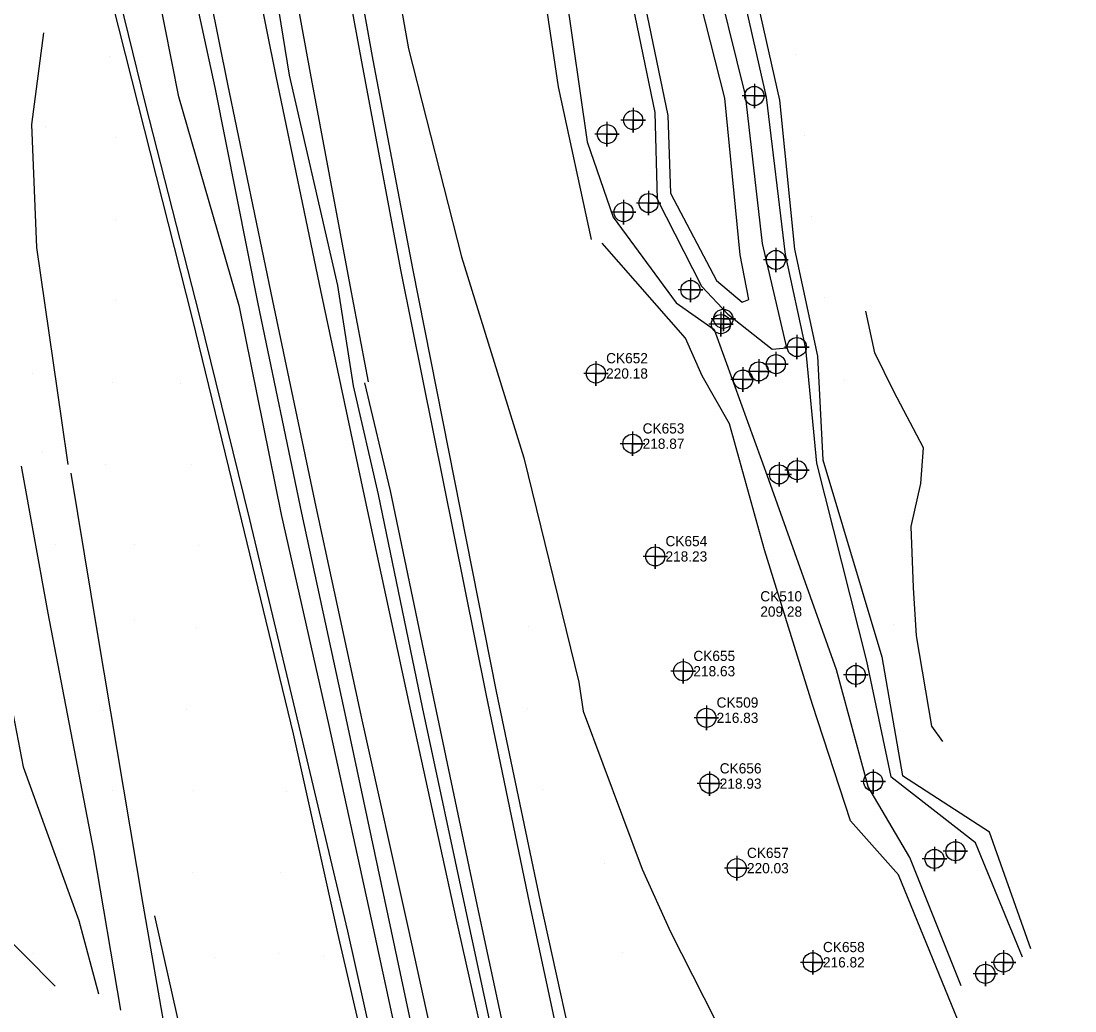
# Model space of a CAD drawing. Extents: x 1941547 to 1942851, y 663002 to 668358.
# Drawn here: x 1941984 to 1942242, y 666212 to 666454.4 of the extents above; entities that cross this region are included whole.
import ezdxf

# ---------------------------------------------------------------- set-up
doc = ezdxf.new("R2010")
doc.units = 0
for name, color, linetype in [('CTL GPS Vertical Cogo Elevation', 7, 'Continuous'), ('CTL NGS Vertical CELL', 7, 'Continuous'), ('Exist DTM Breakline Underwater', 7, 'Continuous'), ('Exist DTM Drainline Cogo Elevation', 7, 'Continuous'), ('Exist DTM Regular Point Underwater CELL', 7, 'Continuous'), ('Exist Property Iron Pin Cogo Number', 7, 'Continuous'), ('Exist Roads EOP Cogo Point CELL', 7, 'Continuous'), ('Exist Roads EOT', 7, 'Continuous'), ('Exist Utilities Telephone UG Cable SUE LOS C Cogo Elevation', 7, 'Continuous'), ('Exist Utilities Telephone UG FO SUE LOS C Cogo Elevation', 7, 'Continuous'), ('PH Exist DTM Breakline', 7, 'Continuous'), ('PH Exist DTM Point', 7, 'Continuous')]:
    doc.layers.add(name, color=color, linetype=linetype)

msp = doc.modelspace()

# ---------------------------------------------------------------- linework, layer by layer
at = {"layer": 'CTL NGS Vertical CELL'}
for points in [[(1942135.5, 665887.91), (1942127.19, 665926.67), (1942116.47, 665977.64), (1942106.06, 666031.75), (1942095.67, 666078.28), (1942084.99, 666129.32), (1942073.59, 666178.98), (1942061.57, 666231.07), (1942050.7, 666279.83), (1942038.07, 666332.06), (1942025.94, 666381.57), (1942012.73, 666433.79), (1941999.93, 666484.44)], [(1942137.2, 665888.17), (1942129.75, 665927.19), (1942119.82, 665978.57), (1942108.24, 666032.34), (1942098.02, 666079.16), (1942087.31, 666129.73), (1942075.59, 666179.6), (1942064.03, 666231.55), (1942052.46, 666280.06), (1942040, 666332.34), (1942027.67, 666382.39), (1942014.48, 666434.14), (1942001.98, 666485.22)]]:
    msp.add_lwpolyline(points, dxfattribs=at)
at = {"layer": 'Exist DTM Breakline Underwater'}
for points in [[(1942091.77, 666678.75), (1942095.7, 666642.98), (1942101.32, 666613.67), (1942106.49, 666587.88), (1942111.26, 666546.73), (1942115.87, 666520.01), (1942119.06, 666486.92), (1942117.3, 666461.85), (1942122.58, 666424.87), (1942128.94, 666406.45), (1942144.41, 666385.42), (1942153.71, 666378.9), (1942158.38, 666365.82), (1942167, 666342.2), (1942183.54, 666295.61), (1942191.33, 666267.04)], [(1942132.79, 666462.93), (1942139.14, 666432.09), (1942139.71, 666410.82), (1942150.61, 666389.55), (1942156.99, 666382.62), (1942167.87, 666374.06), (1942171.46, 666374.45), (1942165.54, 666400), (1942161.38, 666436.33), (1942152.92, 666470.32), (1942144.22, 666513.65), (1942142.34, 666548.69)], [(1942144.62, 666548.74), (1942148.17, 666515.06), (1942159.19, 666467.53), (1942166.42, 666435.81), (1942171.04, 666397.24), (1942176, 666374.23), (1942178.76, 666346.16), (1942190.96, 666297.66), (1942196.91, 666269.32)], [(1942229.17, 666225.2), (1942217.66, 666253.19), (1942196.91, 666269.32)], [(1942214.17, 666218.12), (1942201.55, 666249.54), (1942191.33, 666267.04)]]:
    msp.add_lwpolyline(points, dxfattribs=at)
at = {"layer": 'Exist DTM Drainline Cogo Elevation'}
for points in [[(1942124.73, 666371.13), (1942124.73, 666365.13), (1942124.73, 666368.13), (1942127.73, 666368.13), (1942121.73, 666368.13)], [(1942124.73, 666371.13), (1942124.73, 666365.13), (1942124.73, 666368.13), (1942127.73, 666368.13), (1942121.73, 666368.13)], [(1942133.67, 666353.93), (1942133.67, 666347.93), (1942133.67, 666350.93), (1942136.67, 666350.93), (1942130.67, 666350.93)], [(1942133.67, 666353.93), (1942133.67, 666347.93), (1942133.67, 666350.93), (1942136.67, 666350.93), (1942130.67, 666350.93)], [(1942139.26, 666326.32), (1942139.26, 666320.32), (1942139.26, 666323.32), (1942142.26, 666323.32), (1942136.26, 666323.32)], [(1942139.26, 666326.32), (1942139.26, 666320.32), (1942139.26, 666323.32), (1942142.26, 666323.32), (1942136.26, 666323.32)], [(1942146.09, 666298.21), (1942146.09, 666292.21), (1942146.09, 666295.21), (1942149.09, 666295.21), (1942143.09, 666295.21)], [(1942146.09, 666298.21), (1942146.09, 666292.21), (1942146.09, 666295.21), (1942149.09, 666295.21), (1942143.09, 666295.21)], [(1942151.77, 666286.79), (1942151.77, 666280.79), (1942151.77, 666283.79), (1942154.77, 666283.79), (1942148.77, 666283.79)], [(1942152.54, 666270.67), (1942152.54, 666264.67), (1942152.54, 666267.67), (1942155.54, 666267.67), (1942149.54, 666267.67)], [(1942152.54, 666270.67), (1942152.54, 666264.67), (1942152.54, 666267.67), (1942155.54, 666267.67), (1942149.54, 666267.67)], [(1942159.21, 666249.97), (1942159.21, 666243.97), (1942159.21, 666246.97), (1942162.21, 666246.97), (1942156.21, 666246.97)], [(1942159.21, 666249.97), (1942159.21, 666243.97), (1942159.21, 666246.97), (1942162.21, 666246.97), (1942156.21, 666246.97)], [(1942177.81, 666226.9), (1942177.81, 666220.9), (1942177.81, 666223.9), (1942180.81, 666223.9), (1942174.81, 666223.9)], [(1942177.81, 666226.9), (1942177.81, 666220.9), (1942177.81, 666223.9), (1942180.81, 666223.9), (1942174.81, 666223.9)]]:
    msp.add_lwpolyline(points, dxfattribs=at)
for centre in [(1942124.73, 666368.13), (1942124.73, 666368.13), (1942133.67, 666350.93), (1942133.67, 666350.93), (1942139.26, 666323.32), (1942139.26, 666323.32), (1942146.09, 666295.21), (1942146.09, 666295.21), (1942151.77, 666283.79), (1942152.54, 666267.67), (1942152.54, 666267.67), (1942159.21, 666246.97), (1942159.21, 666246.97), (1942177.81, 666223.9), (1942177.81, 666223.9)]:
    msp.add_circle(centre, 2.34, dxfattribs=at)
at = {"layer": 'Exist DTM Regular Point Underwater CELL'}
for points in [[(1942163.51, 666439.1), (1942163.51, 666433.1), (1942163.51, 666436.1), (1942166.51, 666436.1), (1942160.51, 666436.1)], [(1942133.86, 666433.19), (1942133.86, 666427.19), (1942133.86, 666430.19), (1942136.86, 666430.19), (1942130.86, 666430.19)], [(1942127.44, 666429.74), (1942127.44, 666423.74), (1942127.44, 666426.74), (1942130.44, 666426.74), (1942124.44, 666426.74)], [(1942137.63, 666412.88), (1942137.63, 666406.88), (1942137.63, 666409.88), (1942140.63, 666409.88), (1942134.63, 666409.88)], [(1942131.5, 666410.64), (1942131.5, 666404.64), (1942131.5, 666407.64), (1942134.5, 666407.64), (1942128.5, 666407.64)], [(1942168.76, 666398.94), (1942168.76, 666392.94), (1942168.76, 666395.94), (1942171.76, 666395.94), (1942165.76, 666395.94)], [(1942147.87, 666391.59), (1942147.87, 666385.59), (1942147.87, 666388.59), (1942150.87, 666388.59), (1942144.87, 666388.59)], [(1942155.92, 666384.51), (1942155.92, 666378.51), (1942155.92, 666381.51), (1942158.92, 666381.51), (1942152.92, 666381.51)], [(1942155.33, 666383.22), (1942155.33, 666377.22), (1942155.33, 666380.22), (1942158.33, 666380.22), (1942152.33, 666380.22)], [(1942173.92, 666377.61), (1942173.92, 666371.61), (1942173.92, 666374.61), (1942176.92, 666374.61), (1942170.92, 666374.61)], [(1942168.8, 666373.41), (1942168.8, 666367.41), (1942168.8, 666370.41), (1942171.8, 666370.41), (1942165.8, 666370.41)], [(1942164.63, 666371.64), (1942164.63, 666365.64), (1942164.63, 666368.64), (1942167.63, 666368.64), (1942161.63, 666368.64)], [(1942160.73, 666369.64), (1942160.73, 666363.64), (1942160.73, 666366.64), (1942163.73, 666366.64), (1942157.73, 666366.64)], [(1942173.97, 666347.46), (1942173.97, 666341.46), (1942173.97, 666344.46), (1942176.97, 666344.46), (1942170.97, 666344.46)], [(1942169.57, 666346.42), (1942169.57, 666340.42), (1942169.57, 666343.42), (1942172.57, 666343.42), (1942166.57, 666343.42)], [(1942188.34, 666297.29), (1942188.34, 666291.29), (1942188.34, 666294.29), (1942191.34, 666294.29), (1942185.34, 666294.29)], [(1942192.6, 666271.17), (1942192.6, 666265.17), (1942192.6, 666268.17), (1942195.6, 666268.17), (1942189.6, 666268.17)], [(1942207.61, 666252.23), (1942207.61, 666246.23), (1942207.61, 666249.23), (1942210.61, 666249.23), (1942204.61, 666249.23)], [(1942212.73, 666254.11), (1942212.73, 666248.11), (1942212.73, 666251.11), (1942215.73, 666251.11), (1942209.73, 666251.11)], [(1942224.51, 666226.87), (1942224.51, 666220.87), (1942224.51, 666223.87), (1942227.51, 666223.87), (1942221.51, 666223.87)], [(1942220.06, 666224.09), (1942220.06, 666218.09), (1942220.06, 666221.09), (1942223.06, 666221.09), (1942217.06, 666221.09)]]:
    msp.add_lwpolyline(points, dxfattribs=at)
for centre in [(1942163.51, 666436.1), (1942133.86, 666430.19), (1942127.44, 666426.74), (1942137.63, 666409.88), (1942131.5, 666407.64), (1942168.76, 666395.94), (1942147.87, 666388.59), (1942155.92, 666381.51), (1942155.33, 666380.22), (1942173.92, 666374.61), (1942164.63, 666368.64), (1942168.8, 666370.41), (1942160.73, 666366.64), (1942169.57, 666343.42), (1942173.97, 666344.46), (1942188.34, 666294.29), (1942192.6, 666268.17), (1942212.73, 666251.11), (1942207.61, 666249.23), (1942224.51, 666223.87), (1942220.06, 666221.09)]:
    msp.add_circle(centre, 2.34, dxfattribs=at)
at = {"layer": 'Exist Property Iron Pin Cogo Number'}
msp.add_lwpolyline([(1942228.27, 665631.91), (1942215.35, 665690.54), (1942203.38, 665744.37), (1942193.36, 665791.05), (1942181.96, 665842.56), (1942170.96, 665893.33), (1942160.58, 665938.17), (1942155.29, 665961.96), (1942149.62, 665986.57), (1942137.61, 666038.72), (1942126.12, 666087.51), (1942115.02, 666136.31), (1942103.6, 666187.08), (1942093.09, 666235.61), (1942082.3, 666286.44), (1942071.51, 666338.53), (1942065.4, 666365.11), (1942061.56, 666389.7), (1942049.68, 666441.21), (1942041.5, 666492.09), (1942031.83, 666544.21), (1942023.2, 666595.06), (1942013.62, 666656.61), (1942008.43, 666689.96)], dxfattribs=at)
at = {"layer": 'Exist Roads EOT'}
for points in [[(1942239.89, 665634.47), (1942227.05, 665692.43), (1942215.28, 665746.03), (1942204.9, 665793.1), (1942193.81, 665844.48), (1942182.41, 665896.46), (1942173.11, 665940.53), (1942162.51, 665989.38), (1942151.29, 666040.92), (1942140.43, 666090.67), (1942129.8, 666139.39), (1942119.07, 666189.07), (1942108.58, 666238.14), (1942097.82, 666289.68), (1942077.07, 666393.11), (1942067.43, 666444.43), (1942058.06, 666495.58), (1942049.26, 666547.02), (1942041.05, 666598.14), (1942031.78, 666658.51), (1942026.7, 666693.35)], [(1942216.33, 665631.64), (1942203.63, 665688.68), (1942191.56, 665741.16), (1942181.15, 665788.55), (1942170.15, 665839.04), (1942158.52, 665891.09), (1942148.46, 665935.11), (1942136.79, 665984.14), (1942124.38, 666035.44), (1942112.67, 666084.11), (1942101.18, 666132.69), (1942089.27, 666184.63), (1942078.82, 666232.22), (1942067.51, 666283.26), (1942056.28, 666335.48), (1942045.64, 666385.95), (1942034.6, 666439.01), (1942024.01, 666491.71), (1942014.76, 666541.49), (1942006.11, 666591.53), (1942001.31, 666620.24), (1941993.82, 666637.67), (1941979.79, 666649.91), (1941961.73, 666657.29)], [(1942154.73, 665961.88), (1942148.9, 665986.47), (1942136.37, 666038.07), (1942124.51, 666087.33), (1942112.95, 666135.81), (1942101.29, 666186.74), (1942090.44, 666235.06), (1942079.42, 666285.53), (1942068.09, 666338.16), (1942062.34, 666365.05), (1942057.42, 666388.45), (1942046.52, 666440.57), (1942036.47, 666490.47), (1942026.54, 666543.55), (1942017.93, 666593.73), (1942007.82, 666655.78)], [(1942069.09, 666366.11), (1942064.53, 666389.77), (1942054.87, 666441.71), (1942045.44, 666493.08), (1942037.04, 666544.89), (1942028.85, 666595.58), (1942019.74, 666656.24)], [(1942155.67, 665962.14), (1942150.22, 665986.74), (1942138.88, 666038.57), (1942127.93, 666087.9), (1942117.32, 666136.64), (1942106.41, 666187.82), (1942095.96, 666236.54), (1942085.34, 666286.97), (1942074.48, 666339.36), (1942068.19, 666365.82)]]:
    msp.add_lwpolyline(points, dxfattribs=at)
at = {"layer": 'Exist Utilities Telephone UG Cable SUE LOS C Cogo Elevation'}
for points in [[(1942241.99, 665634.93), (1942229.18, 665693.32), (1942218.46, 665746.7), (1942209.27, 665793.91), (1942197.95, 665845.25), (1942186.36, 665897.34), (1942176.03, 665941.11), (1942165.47, 665989.95), (1942154.18, 666041.36), (1942143.37, 666091.41), (1942132.79, 666139.63), (1942122, 666189.48), (1942111.14, 666238.84), (1942100.41, 666290.27), (1942079.89, 666393.87), (1942070.21, 666444.86), (1942060.95, 666496.14), (1942052.29, 666547.35), (1942044.06, 666598.94), (1942035.22, 666658.38), (1942029.81, 666693.65)], [(1942213.99, 665632.37), (1942202.16, 665688.24), (1942190.02, 665740.92), (1942178.65, 665787.73), (1942166.53, 665839.16), (1942154.86, 665890.17), (1942143.77, 665934.31), (1942131.73, 665982.91), (1942119.44, 666034.59), (1942108.8, 666082.94), (1942097.26, 666132.24), (1942084.85, 666183.55), (1942074.65, 666231.51), (1942063.8, 666282.56), (1942052.72, 666333.95), (1942042.01, 666385.23), (1942031.54, 666438.14), (1942020.1, 666490.97), (1942010.35, 666540.81), (1942001.86, 666591.1), (1941996.76, 666619.63), (1941991.94, 666636.36), (1941978.98, 666647.81), (1941961.64, 666654.67)]]:
    msp.add_lwpolyline(points, dxfattribs=at)
at = {"layer": 'Exist Utilities Telephone UG FO SUE LOS C Cogo Elevation'}
msp.add_line((1942025.01, 666198.49), (1942016.74, 666235.33), dxfattribs=at)
for points in [[(1942040.06, 666695.59), (1942044.64, 666660.9), (1942053.37, 666600.34), (1942061.1, 666549.68), (1942070.22, 666496.32), (1942078.82, 666447.64), (1942091.81, 666396.73), (1942107.09, 666347.46), (1942120.54, 666292.55), (1942121.58, 666285.4), (1942136.04, 666246.7), (1942142.99, 666231.38), (1942156.51, 666204.69), (1942176.98, 666157.07), (1942194.89, 666100.26)], [(1942123.62, 666400.94), (1942115.55, 666438.3), (1942109.62, 666478.35), (1942106.9, 666518.05), (1942100.95, 666558.27)], [(1942135.91, 666462.49), (1942142.36, 666431.3), (1942142.96, 666412.28), (1942154.22, 666390.92), (1942160.56, 666385.57), (1942162.15, 666386.27), (1942160.08, 666397.16), (1942156.25, 666435.58), (1942148.06, 666468.05), (1942141.36, 666512.94), (1942138.83, 666547.76)], [(1942148.29, 666548.23), (1942150.62, 666519.14), (1942162.38, 666467.44), (1942169.67, 666435.04), (1942173.32, 666398.58), (1942178.98, 666372.34), (1942180.25, 666347.02), (1942194.7, 666298.74), (1942199.77, 666269.61)], [(1942168.3, 665779.55), (1942157.65, 665834.34), (1942151.92, 665851.93), (1942141.5, 665888.6), (1942135.45, 665929.19), (1942125.9, 665980.59), (1942115.36, 666033.71), (1942104.57, 666081.51), (1942092.84, 666130.71), (1942081.31, 666181.18), (1942070.23, 666232.6), (1942059.43, 666281.93), (1942047.77, 666333.59), (1942037.49, 666384.47), (1942022.61, 666435.89), (1942012.32, 666487.89)], [(1941989.46, 666451.59), (1941986.52, 666429.11), (1941987.75, 666399.02), (1941993.91, 666356.59), (1941995.49, 666345.86)], [(1942187.02, 666258.54), (1942177.78, 666287.03), (1942165.96, 666324.97), (1942157.43, 666355.78), (1942150.74, 666367.59), (1942146.68, 666376.77), (1942126.23, 666400.06)], [(1941900.24, 666359.08), (1941938.41, 666335.83), (1941976.24, 666314.28), (1941984.52, 666271.75), (1941998.11, 666234.11), (1942002.98, 666216.21)], [(1942008.4, 666212.18), (1942001.81, 666251.18), (1941990.63, 666309.45), (1941984.13, 666345.39)], [(1942019.56, 666205.82), (1942013.89, 666238.19), (1942002.78, 666304.16), (1941996.3, 666343.72)], [(1941913.93, 666286.99), (1941962.33, 666248.37), (1941992.34, 666218.07)], [(1942231.16, 666227.23), (1942221.09, 666255.81), (1942199.77, 666269.61)], [(1942214.84, 666205.98), (1942198.8, 666245.36), (1942187.02, 666258.54)]]:
    msp.add_lwpolyline(points, dxfattribs=at)
at = {"layer": 'PH Exist DTM Breakline'}
msp.add_lwpolyline([(1942209.69, 666277.98), (1942206.98, 666281.73), (1942203.18, 666303.89), (1942202.44, 666315.73), (1942201.92, 666330.65), (1942204.3, 666341.15), (1942204.9, 666349.9), (1942197.69, 666363.72), (1942193.01, 666373.22), (1942190.79, 666383.37)], dxfattribs=at)
at = {"layer": 'PH Exist DTM Point'}
for p, q in [((1942005.65, 666445.85), (1942005.65, 666445.85)), ((1942173.62, 666446.38), (1942173.62, 666446.38)), ((1941989.93, 666428.6), (1941989.93, 666428.6)), ((1942007.13, 666425.95), (1942007.13, 666425.95)), ((1942175.84, 666426.5), (1942175.84, 666426.5)), ((1942177.61, 666406.52), (1942177.61, 666406.52)), ((1942007.13, 666405.95), (1942007.13, 666405.95)), ((1942007.13, 666385.95), (1942007.13, 666385.95)), ((1942180.66, 666386.84), (1942180.66, 666386.84)), ((1941986.75, 666368.04), (1941986.75, 666368.04)), ((1942006.5, 666365.91), (1942006.5, 666365.91)), ((1942023.14, 666365.68), (1942023.14, 666365.68)), ((1942185.69, 666366.29), (1942185.69, 666366.29)), ((1941989.24, 666348.82), (1941989.24, 666348.82)), ((1942004.77, 666345.79), (1942004.77, 666345.79)), ((1942025.71, 666345.85), (1942025.71, 666345.85)), ((1941992.5, 666326.3), (1941992.5, 666326.3)), ((1942011.87, 666326.29), (1942011.87, 666326.29)), ((1942027.42, 666326.11), (1942027.42, 666326.11)), ((1942011.76, 666307.76), (1942011.76, 666307.76)), ((1942026.99, 666306.03), (1942026.99, 666306.03)), ((1942108.27, 666306.04), (1942108.27, 666306.04)), ((1942197.57, 666306.64), (1942197.57, 666306.64)), ((1942002.96, 666305.6), (1942002.96, 666305.6)), ((1942004.23, 666285.7), (1942004.23, 666285.7)), ((1942024.62, 666285.78), (1942024.62, 666285.78)), ((1942107.88, 666286), (1942107.88, 666286)), ((1942006.39, 666265.9), (1942006.39, 666265.9)), ((1942026.28, 666265.89), (1942026.28, 666265.89)), ((1942048.95, 666265.79), (1942048.95, 666265.79)), ((1942111.53, 666266.24), (1942111.53, 666266.24)), ((1942126.84, 666248.11), (1942126.84, 666248.11)), ((1942011.6, 666246.24), (1942011.6, 666246.24)), ((1942025.9, 666245.97), (1942025.9, 666245.97)), ((1942047.63, 666245.99), (1942047.63, 666245.99)), ((1941987.13, 666225.97), (1941987.13, 666225.97)), ((1942015.01, 666226.47), (1942015.01, 666226.47)), ((1942047.13, 666225.95), (1942047.13, 666225.95)), ((1942131.32, 666226.23), (1942131.32, 666226.23)), ((1942031.4, 666224.99), (1942031.4, 666224.99)), ((1942058.15, 666225.35), (1942058.15, 666225.35))]:
    msp.add_line(p, q, dxfattribs=at)

# ---------------------------------------------------------------- texts
at = {"layer": 'CTL GPS Vertical Cogo Elevation'}
for s, p in [('CK652', (1942127.23, 666370.63)), ('CK653', (1942136.17, 666353.43)), ('CK654', (1942141.76, 666325.82)), ('CK510', (1942164.97, 666312.31)), ('CK655', (1942148.59, 666297.71)), ('CK509', (1942154.27, 666286.29)), ('CK656', (1942155.04, 666270.17)), ('CK657', (1942161.71, 666249.47)), ('CK658', (1942180.31, 666226.4))]:
    msp.add_text(s, height=2.5, dxfattribs=at).set_placement(p)
at = {"layer": 'Exist Roads EOP Cogo Point CELL'}
for s, p in [('220.18', (1942127.23, 666366.88)), ('218.87', (1942136.17, 666349.68)), ('218.23', (1942141.76, 666322.07)), ('209.28', (1942164.97, 666308.56)), ('218.63', (1942148.59, 666293.96)), ('216.83', (1942154.27, 666282.54)), ('218.93', (1942155.04, 666266.42)), ('220.03', (1942161.71, 666245.72)), ('216.82', (1942180.31, 666222.65))]:
    msp.add_text(s, height=2.5, dxfattribs=at).set_placement(p)

doc.saveas('drawing.dxf')
